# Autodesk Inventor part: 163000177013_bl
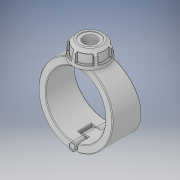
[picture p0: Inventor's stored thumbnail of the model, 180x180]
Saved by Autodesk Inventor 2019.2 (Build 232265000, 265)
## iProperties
Created: 2022-02
Part Number: 163000177013_bl
Material: Generic
Description: Plassadle Threaded 177x1 1/4''
Document SubType Name: Modeling
Designer: comp2
Density: 1 g/cm^3
Appearance: Default
Author: comp2
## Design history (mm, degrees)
derived "16300.ipt"
feature "Solid1::16300.ipt" dims "ScaleForDerivedMember" = 10
feature "Solid2::16300.ipt" dims "ScaleForDerivedMember" = 10
feature "Solid3::16300.ipt" dims "ScaleForDerivedMember" = 10
feature "Solid4::16300.ipt" dims "ScaleForDerivedMember" = 10
tag "TaggingFeature1"
body "Solid1"
body "Solid2"
body "Solid3"
body "Solid4"
other parameters: "d0" = 177 [user parameter], "d3" = 88.5 [user parameter], "d7" = 209 [user parameter], "d8" = 85 deg [user parameter], "d9" = 45 deg [user parameter], "d10" = 102 [user parameter], "d11" = 49 [user parameter], "d12" = 31.57 [user parameter], "d13" = 42.84 [user parameter], "d14" = 58.428 [user parameter], "d42" = 4.3 [user parameter], "d49" = 4.4 [user parameter], "d51" = 0 [user parameter], "d52" = 30.1 [user parameter], "d53" = 121 [user parameter], "d54" = 38.5 [user parameter], "d55" = 0 [user parameter], "d56" = 22 [user parameter], "d57" = 22 [user parameter], "d59" = 0 [user parameter], "d61" = 0 [user parameter], "d62" = 38.5 [user parameter], "d63" = 0 [user parameter], "d65" = 0 [user parameter], "d67" = 0 [user parameter], "d69" = 0 [user parameter], "d70" = 1 [user parameter], "d71" = 105.6 [user parameter], "d72" = 0 [user parameter], "d73" = 2 [user parameter], "d78" = 86.7 [user parameter], "d79" = 5.1 [user parameter], "d80" = 60 deg [user parameter], "d81" = 5.1 [user parameter], "d84" = 0 [user parameter], "d85" = 1 [user parameter], "d87" = 360 deg [user parameter], "d122" = 61 [user parameter], "d124" = 42.80128 [user parameter], "d125" = 2.255 [user parameter], "d127" = 264 [user parameter], "d129" = 38.952 [user parameter], "d130" = 33.1092 [user parameter], "d131" = 39.65 [user parameter], "d132" = 45 deg [user parameter], "d133" = 27.755 [user parameter], "d134" = 19.476 [user parameter], "d136" = 0 [user parameter], "d138" = 0 [user parameter], "d" = 177 [user parameter], "d1" = 25 [user parameter], "E_" = 54 [user parameter], "E1" = 102 [user parameter], "H1" = 264 [user parameter], "H2" = 61 [user parameter], "H3" = 78 [user parameter], "H_costum" = 49 [user parameter], "Rp" = 38.952 [user parameter], "d128" = 45.1 [user parameter]
